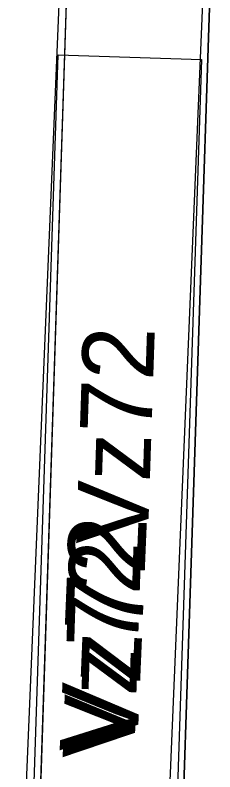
# Model space of a CAD drawing. Extents: x 647787 to 668496, y 640478 to 654412.
# Drawn here: x 662769.99 to 662778.35, y 647352.03 to 647383.75 of the extents above; entities that cross this region are included whole.
import ezdxf

# ---------------------------------------------------------------- set-up
doc = ezdxf.new("R2010")
doc.units = 0
for name, color, linetype in [('TEMP_DETECTION ZONE', 7, 'Continuous'), ('TEMP_DETECTION ZONE_Stage 2', 7, 'Continuous'), ('TEMP_DETECTION ZONE_STAGE 3', 7, 'Continuous'), ('TEMP_DETECTION_ZONE_STAGE 4', 7, 'Continuous'), ('TEMP_DETECTION_ZONE_STAGE 5', 7, 'Continuous'), ('TEMP_SIGNAL_POLES_STAGE 1B', 7, 'Continuous')]:
    doc.layers.add(name, color=color, linetype=linetype)

msp = doc.modelspace()

# ---------------------------------------------------------------- linework, layer by layer
at = {"layer": 'TEMP_DETECTION ZONE'}
msp.add_lwpolyline([(662770.711, 647341.082), (662776.708, 647340.885), (662778.352, 647390.858), (662772.355, 647391.055)], close=True, dxfattribs=at)
msp.add_lwpolyline([(662770.711, 647341.082), (662776.708, 647340.885), (662778.352, 647390.858), (662772.355, 647391.055)], close=True, dxfattribs=at)
at = {"layer": 'TEMP_DETECTION ZONE_Stage 2'}
msp.add_lwpolyline([(662776.71, 647340.887), (662770.713, 647341.084), (662772.357, 647391.057), (662778.354, 647390.86)], close=True, dxfattribs=at)
at = {"layer": 'TEMP_DETECTION ZONE_STAGE 3'}
msp.add_lwpolyline([(662776.71, 647340.887), (662770.713, 647341.084), (662772.357, 647391.057), (662778.354, 647390.86)], close=True, dxfattribs=at)
at = {"layer": 'TEMP_DETECTION_ZONE_STAGE 4'}
msp.add_lwpolyline([(662776.71, 647340.887), (662770.713, 647341.084), (662772.357, 647391.057), (662778.354, 647390.86)], close=True, dxfattribs=at)
at = {"layer": 'TEMP_DETECTION_ZONE_STAGE 5'}
msp.add_lwpolyline([(662776.146, 647331.916), (662770.149, 647332.113), (662771.793, 647382.086), (662777.79, 647381.889)], close=True, dxfattribs=at)
at = {"layer": 'TEMP_SIGNAL_POLES_STAGE 1B'}
msp.add_lwpolyline([(662775.983, 647339.992), (662769.988, 647340.242), (662772.077, 647390.199), (662778.072, 647389.948)], close=True, dxfattribs=at)

# ---------------------------------------------------------------- texts
at = {"layer": 'TEMP_DETECTION ZONE_Stage 2'}
msp.add_text('Vz72', height=3, rotation=88.1157, dxfattribs=at).set_placement((662775.541, 647361.498))
at = {"layer": 'TEMP_DETECTION ZONE_STAGE 3'}
msp.add_text('Vz72', height=3, rotation=88.1157, dxfattribs=at).set_placement((662775.541, 647361.498))
at = {"layer": 'TEMP_DETECTION_ZONE_STAGE 4'}
msp.add_text('Vz72', height=3, rotation=88.1157, dxfattribs=at).set_placement((662775.541, 647361.498))
at = {"layer": 'TEMP_DETECTION_ZONE_STAGE 5'}
msp.add_text('Vz72', height=3, rotation=88.1157, dxfattribs=at).set_placement((662774.976, 647352.527))
at = {"layer": 'TEMP_SIGNAL_POLES_STAGE 1B'}
msp.add_text('Vz72', height=3.25, rotation=87.6052, dxfattribs=at).set_placement((662775.098, 647352.775))

doc.saveas('drawing.dxf')
